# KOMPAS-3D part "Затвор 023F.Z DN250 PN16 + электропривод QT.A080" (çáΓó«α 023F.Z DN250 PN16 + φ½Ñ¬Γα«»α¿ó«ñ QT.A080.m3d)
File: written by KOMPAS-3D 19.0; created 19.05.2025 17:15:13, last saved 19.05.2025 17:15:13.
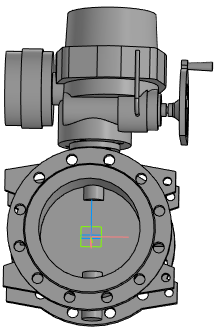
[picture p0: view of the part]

Document properties: Полное имя файла: Затвор 023F.Z DN250 PN16 + электропривод QT.A080.a3d

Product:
- Part/product: Затвор 023F.Z DN250 PN16 + электропривод QT.A080
    Масса: 200.398

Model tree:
1. Операция без истории:1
